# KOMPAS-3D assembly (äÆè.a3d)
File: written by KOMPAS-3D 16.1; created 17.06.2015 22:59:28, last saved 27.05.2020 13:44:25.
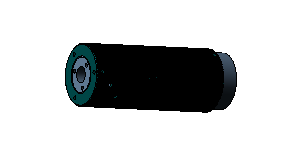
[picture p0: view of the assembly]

Referenced files in D:\Новая папка\работа\Чертежи\Компенсатор\Пламегаситель Свечка\: Компенсатор.m3d, Колпак.m3d
Referenced files: GRAPHIC.TDP
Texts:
  Body Specification ( left align )
  Body Specificaton ( centered )
  Zebra 002
  (ф) Zebra 002 ТДК
  Zebra 001
  (-) Zebra 001 Колпак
